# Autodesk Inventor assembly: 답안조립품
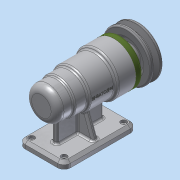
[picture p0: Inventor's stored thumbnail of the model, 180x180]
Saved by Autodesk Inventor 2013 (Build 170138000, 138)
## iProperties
Created: 2016-06
Part Number: 답안조립품
Document SubType Name: Assembly
Designer: dgall
Author: dgall
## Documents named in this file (12)
- C:\Users\dgall\Desktop\460607V1011\답안조립품.iam
- C:\Users\dgall\Desktop\460607V1011\V벨트풀리.ipt
- C:\Users\dgall\Desktop\460607V1011\멈춤나사 M3x8.ipt
- C:\Users\dgall\Desktop\460607V1011\베어링 6004.ipt
- C:\Users\dgall\Desktop\460607V1011\베어링 51202.ipt
- C:\Users\dgall\Desktop\460607V1011\본체.ipt
- C:\Users\dgall\Desktop\460607V1011\볼트 M4 x 12.ipt
- C:\Users\dgall\Desktop\460607V1011\어댑터슬리브.ipt
- C:\Users\dgall\Desktop\460607V1011\오일 실.ipt
- C:\Users\dgall\Desktop\460607V1011\축.ipt
- C:\Users\dgall\Desktop\460607V1011\커버.ipt
- C:\Users\dgall\Desktop\460607V1011\키 5 x 5 x 16.ipt
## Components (5 placed, 2 different names)
1. V벨트풀리:1 — 플러쉬:1
2. ISO 4762 M4 x 12:1
3. ISO 4762 M4 x 12:2
4. ISO 4762 M4 x 12:3
5. ISO 4762 M4 x 12:4
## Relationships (1: Flush 1)
- 플러쉬:1 [Flush]: V벨트풀리:1
